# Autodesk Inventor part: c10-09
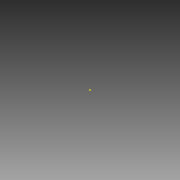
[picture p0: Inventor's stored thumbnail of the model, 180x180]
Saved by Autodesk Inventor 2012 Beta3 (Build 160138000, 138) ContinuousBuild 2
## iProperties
Created: 2011-01
Part Number: c10-09
Material: Steel, Mild
Document SubType Name: Sheet Metal
Designer: Beta-8540w
Density: 7.86 g/cm^3
Sheet Metal Rule: Steel - 16ga
Author: Beta-8540w
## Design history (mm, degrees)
sketch "Sketch1"
  geometry: 1 further point
other parameters: "Thickness" = 1.524 (derived), "BendRadius" = 1.524 (= Thickness), "BendReliefWidth" = 1.524 (= Thickness), "BendReliefDepth" = 0.762 (= 0.5 x Thickness), "CornerReliefSize" = 6.096 (= 4 x Thickness), "SeamGap" = 0.01, "MinimumRemnant" = 3.048 (= 2 x Thickness), "TransitionRadius" = 1.524 (= BendRadius), "JacobiRadiusSize" = 1.524 (= BendRadius), "GapSize" = 0.762 (= 0.5 x Thickness)
